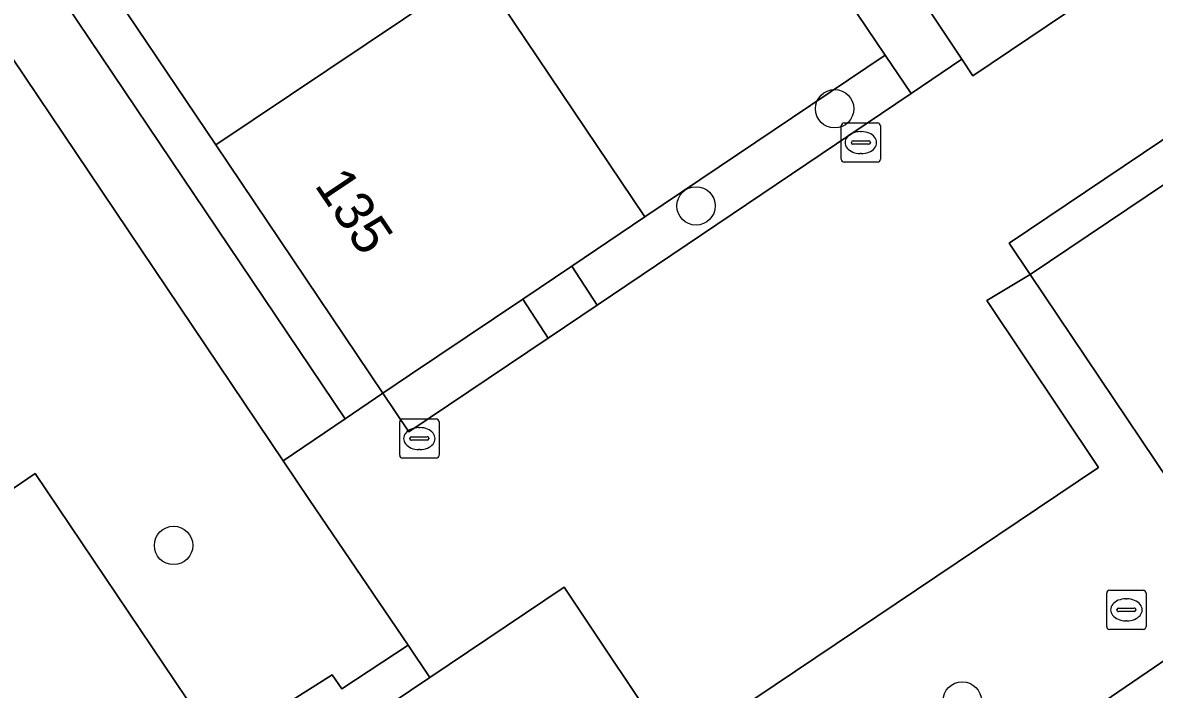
# Model space of a CAD drawing. Extents: x 158793 to 159888, y 384317 to 385256.
# Drawn here: x 159193.03 to 159221.85, y 384582.61 to 384599.59 of the extents above; entities that cross this region are included whole.
import ezdxf

# ---------------------------------------------------------------- set-up
doc = ezdxf.new("R2010")
doc.units = 0
for name, color, linetype in [('IMGEO_Boom', 7, 'Continuous'), ('IMGEO_Erf', 7, 'Continuous'), ('IMGEO_Groenvoorziening', 7, 'Continuous'), ('IMGEO_Kolk', 7, 'Continuous'), ('IMGEO_Pand', 7, 'Continuous'), ('IMGEO_Pand_nummerreeks', 7, 'Continuous'), ('IMGEO_Rijbaan_lokaal_open', 7, 'Continuous'), ('IMGEO_Rioolput', 7, 'Continuous'), ('IMGEO_Voetpad_gesloten', 7, 'Continuous'), ('IMGEO_Voetpad_open', 7, 'Continuous')]:
    doc.layers.add(name, color=color, linetype=linetype)

msp = doc.modelspace()

# ---------------------------------------------------------------- linework, layer by layer
at = {"layer": 'IMGEO_Boom'}
for centre in [(159213.705, 384597.396), (159210.177, 384594.923), (159196.875, 384586.273), (159216.954, 384582.311)]:
    msp.add_circle(centre, 0.489, dxfattribs=at)
at = {"layer": 'IMGEO_Erf'}
msp.add_lwpolyline([(159189.5, 384636.563), (159183.38, 384632.567), (159187.63, 384626.246), (159191.879, 384619.926), (159196.129, 384613.605), (159200.378, 384607.285), (159204.628, 384600.965), (159208.877, 384594.644), (159214.996, 384598.764)], close=True, dxfattribs=at)
at = {"layer": 'IMGEO_Groenvoorziening'}
for points in [[(159245.073, 384674.375), (159284.084, 384616.156), (159275.927, 384610.681), (159273.311, 384614.477), (159265.419, 384609.219), (159264.866, 384609.954), (159259.381, 384606.275), (159260.51, 384604.607), (159254.969, 384600.946), (159255.845, 384599.623), (159254.824, 384599.006), (159227.4, 384580.648), (159223.505, 384586.498), (159223.273, 384586.343), (159218.681, 384593.177), (159217.583, 384592.512), (159220.423, 384588.255), (159209.629, 384581), (159206.819, 384585.213), (159203.401, 384582.912), (159198.891, 384579.876)], [(159218.552, 384602.596), (159215.624, 384600.655), (159216.947, 384598.656), (159217.228, 384598.232), (159220.077, 384600.155)], [(159208.686, 384574.19), (159223.666, 384584.415), (159228.726, 384576.872), (159242.691, 384586.237)]]:
    msp.add_lwpolyline(points, dxfattribs=at)
for points in [[(159184.844, 384610.474), (159149.937, 384586.778), (159139.375, 384579.667), (159141.123, 384576.932), (159150.625, 384583.433), (159151.747, 384581.759), (159165.041, 384590.724), (159170.605, 384582.437), (159174.689, 384585.159), (159179.297, 384578.512), (159193.347, 384588.107), (159197.808, 384581.483), (159198.988, 384582.307), (159199.249, 384581.925), (159200.917, 384582.98), (159201.158, 384582.618), (159202.847, 384583.73), (159200.329, 384587.446), (159199.667, 384588.43)], [(159215.656, 384597.786), (159214.996, 384598.764), (159208.877, 384594.644), (159207.011, 384593.387), (159207.663, 384592.398)], [(159206.415, 384591.557), (159205.763, 384592.546), (159202.885, 384590.608), (159202.203, 384590.149), (159202.865, 384589.164)]]:
    msp.add_lwpolyline(points, close=True, dxfattribs=at)
at = {"layer": 'IMGEO_Kolk'}
for p, q in [((159213.873, 384596.109), (159213.873, 384596.961)), ((159213.948, 384597.035), (159214.8, 384597.035)), ((159214.874, 384596.961), (159214.874, 384596.109)), ((159214.361, 384596.815), (159214.386, 384596.815)), ((159214.132, 384596.529), (159214.132, 384596.541)), ((159214.57, 384596.492), (159214.172, 384596.492)), ((159214.175, 384596.578), (159214.573, 384596.578)), ((159214.616, 384596.541), (159214.616, 384596.529)), ((159214.384, 384596.255), (159214.359, 384596.255)), ((159214.8, 384596.035), (159213.948, 384596.035)), ((159202.707, 384589.496), (159203.559, 384589.496)), ((159202.632, 384588.57), (159202.632, 384589.422)), ((159203.12, 384589.276), (159203.145, 384589.276)), ((159203.633, 384589.422), (159203.633, 384588.57)), ((159202.891, 384588.99), (159202.891, 384589.002)), ((159203.329, 384588.953), (159202.931, 384588.953)), ((159202.934, 384589.039), (159203.332, 384589.039)), ((159203.375, 384589.002), (159203.375, 384588.99)), ((159203.143, 384588.716), (159203.118, 384588.716)), ((159203.559, 384588.496), (159202.707, 384588.496))]:
    msp.add_line(p, q, dxfattribs=at)
for points in [[(159213.873, 384596.109), (159213.873, 384596.961)], [(159213.948, 384597.035), (159214.8, 384597.035)], [(159214.874, 384596.961), (159214.874, 384596.109)], [(159214.8, 384596.035), (159213.948, 384596.035)], [(159202.707, 384589.496), (159203.559, 384589.496)], [(159202.632, 384588.57), (159202.632, 384589.422)], [(159203.633, 384589.422), (159203.633, 384588.57)], [(159203.559, 384588.496), (159202.707, 384588.496)]]:
    msp.add_lwpolyline(points, dxfattribs=at)
for centre, radius, start, end in [((159213.95, 384596.959), 0.0765, 91.552, 178.448), ((159213.95, 384596.959), 0.0765, 91.552, 178.448), ((159214.798, 384596.959), 0.0765, 1.552, 88.448), ((159214.798, 384596.959), 0.0765, 1.552, 88.448), ((159214.172, 384596.538), 0.0403, 85.8775, 175.7526), ((159214.169, 384596.528), 0.0366, 178.938, 274.7102), ((159214.573, 384596.535), 0.043, 264.8664, 352.4533), ((159214.577, 384596.54), 0.0386, 1.7309, 96.639), ((159213.95, 384596.111), 0.0765, 181.552, 268.448), ((159213.95, 384596.111), 0.0765, 181.552, 268.448), ((159214.798, 384596.111), 0.0765, 271.552, 358.448), ((159214.798, 384596.111), 0.0765, 271.552, 358.448), ((159202.709, 384589.42), 0.0765, 91.552, 178.448), ((159202.709, 384589.42), 0.0765, 91.552, 178.448), ((159203.557, 384589.42), 0.0765, 1.552, 88.448), ((159203.557, 384589.42), 0.0765, 1.552, 88.448), ((159202.931, 384588.999), 0.0403, 85.8775, 175.7526), ((159202.928, 384588.989), 0.0366, 178.938, 274.7102), ((159203.332, 384588.996), 0.043, 264.8664, 352.4533), ((159203.336, 384589.001), 0.0386, 1.7309, 96.639), ((159202.709, 384588.572), 0.0765, 181.552, 268.448), ((159202.709, 384588.572), 0.0765, 181.552, 268.448), ((159203.557, 384588.572), 0.0765, 271.552, 358.448), ((159203.557, 384588.572), 0.0765, 271.552, 358.448)]:
    msp.add_arc(centre, radius, start, end, dxfattribs=at)
for centre, major_axis, ratio, start_param, end_param in [((159214.36, 384596.535), (-0.387, 0.002), 0.722429, 4.712389, 7.853982), ((159214.385, 384596.535), (-0.39, 0.002), 0.717154, 1.570796, 4.712389), ((159203.119, 384588.996), (-0.387, 0.002), 0.722429, 4.712389, 7.853982), ((159203.144, 384588.996), (-0.39, 0.002), 0.717154, 1.570796, 4.712389)]:
    msp.add_ellipse(centre, major_axis=major_axis, ratio=ratio, start_param=start_param, end_param=end_param, dxfattribs=at)
at = {"layer": 'IMGEO_Pand'}
for points in [[(159200.378, 384607.285), (159193.701, 384602.796), (159197.95, 384596.475), (159204.628, 384600.965)], [(159204.628, 384600.965), (159197.95, 384596.475), (159202.203, 384590.149), (159202.885, 384590.608), (159205.763, 384592.546), (159207.011, 384593.387), (159208.877, 384594.644)], [(159225.624, 384597.848), (159218.681, 384593.177), (159223.273, 384586.343), (159223.505, 384586.498), (159230.234, 384590.995)]]:
    msp.add_lwpolyline(points, close=True, dxfattribs=at)
at = {"layer": 'IMGEO_Rijbaan_lokaal_open'}
msp.add_lwpolyline([(159220.077, 384600.155), (159217.228, 384598.232), (159216.947, 384598.656), (159215.656, 384597.786), (159207.663, 384592.398), (159206.415, 384591.557), (159202.865, 384589.164), (159202.203, 384590.149), (159201.24, 384589.496), (159199.667, 384588.43), (159200.329, 384587.446), (159202.847, 384583.73), (159203.401, 384582.912), (159206.819, 384585.213), (159209.629, 384581), (159220.423, 384588.255), (159217.583, 384592.512), (159218.681, 384593.177), (159218.146, 384593.974), (159245.904, 384612.649)], dxfattribs=at)
at = {"layer": 'IMGEO_Rioolput'}
for p, q in [((159220.708, 384585.133), (159221.56, 384585.133)), ((159220.633, 384584.207), (159220.633, 384585.059)), ((159221.121, 384584.913), (159221.146, 384584.913)), ((159221.634, 384585.059), (159221.634, 384584.207)), ((159220.892, 384584.627), (159220.892, 384584.639)), ((159221.33, 384584.59), (159220.932, 384584.59)), ((159220.935, 384584.676), (159221.333, 384584.676)), ((159221.376, 384584.639), (159221.376, 384584.627)), ((159221.144, 384584.353), (159221.119, 384584.353)), ((159221.56, 384584.133), (159220.708, 384584.133))]:
    msp.add_line(p, q, dxfattribs=at)
for points in [[(159220.708, 384585.133), (159221.56, 384585.133)], [(159220.633, 384584.207), (159220.633, 384585.059)], [(159221.634, 384585.059), (159221.634, 384584.207)], [(159221.56, 384584.133), (159220.708, 384584.133)]]:
    msp.add_lwpolyline(points, dxfattribs=at)
for centre, radius, start, end in [((159220.71, 384585.057), 0.0765, 91.552, 178.448), ((159220.71, 384585.057), 0.0765, 91.552, 178.448), ((159221.558, 384585.057), 0.0765, 1.552, 88.448), ((159221.558, 384585.057), 0.0765, 1.552, 88.448), ((159220.932, 384584.636), 0.0403, 85.8775, 175.7526), ((159220.929, 384584.626), 0.0366, 178.938, 274.7102), ((159221.333, 384584.633), 0.043, 264.8664, 352.4533), ((159221.337, 384584.638), 0.0386, 1.7309, 96.639), ((159220.71, 384584.209), 0.0765, 181.552, 268.448), ((159220.71, 384584.209), 0.0765, 181.552, 268.448), ((159221.558, 384584.209), 0.0765, 271.552, 358.448), ((159221.558, 384584.209), 0.0765, 271.552, 358.448)]:
    msp.add_arc(centre, radius, start, end, dxfattribs=at)
for centre, major_axis, ratio, start_param, end_param in [((159221.12, 384584.633), (-0.387, 0.002), 0.722429, 4.712389, 7.853982), ((159221.145, 384584.633), (-0.39, 0.002), 0.717154, 1.570796, 4.712389)]:
    msp.add_ellipse(centre, major_axis=major_axis, ratio=ratio, start_param=start_param, end_param=end_param, dxfattribs=at)
at = {"layer": 'IMGEO_Voetpad_gesloten'}
for points in [[(159259, 384579.781), (159264.913, 384583.752), (159257.026, 384595.85), (159248.575, 384590.183), (159247.59, 384591.694), (159241.692, 384587.769), (159242.691, 384586.237), (159228.726, 384576.872), (159223.666, 384584.415), (159208.686, 384574.19)], [(159197.808, 384581.483), (159193.347, 384588.107), (159179.297, 384578.512), (159174.689, 384585.159), (159170.605, 384582.437), (159165.041, 384590.724), (159151.747, 384581.759), (159150.625, 384583.433), (159141.123, 384576.932)], [(159198.891, 384579.876), (159203.401, 384582.912), (159202.847, 384583.73), (159201.158, 384582.618), (159200.917, 384582.98), (159199.249, 384581.925)]]:
    msp.add_lwpolyline(points, dxfattribs=at)
at = {"layer": 'IMGEO_Voetpad_open'}
for points in [[(159189.5, 384636.563), (159214.996, 384598.764), (159215.656, 384597.786), (159216.947, 384598.656), (159215.624, 384600.655), (159209.726, 384609.51), (159208.644, 384611.068), (159201.442, 384621.858), (159200.364, 384623.414), (159203.215, 384625.336), (159209.792, 384629.775)], [(159184.844, 384610.474), (159199.667, 384588.43), (159201.24, 384589.496), (159185.263, 384613.249), (159175.767, 384627.444), (159176.706, 384628.077), (159176.084, 384629.066)]]:
    msp.add_lwpolyline(points, dxfattribs=at)
for points in [[(159189.452, 384609.117), (159185.203, 384615.437), (159180.954, 384621.758), (159176.706, 384628.077), (159175.767, 384627.444), (159185.263, 384613.249), (159201.24, 384589.496), (159202.203, 384590.149), (159197.95, 384596.475), (159193.701, 384602.796)], [(159239.509, 384607.189), (159246.451, 384611.86), (159245.904, 384612.649), (159218.146, 384593.974), (159218.681, 384593.177), (159225.624, 384597.848), (159232.566, 384602.519)], [(159207.011, 384593.387), (159205.763, 384592.546), (159206.415, 384591.557), (159207.663, 384592.398)]]:
    msp.add_lwpolyline(points, close=True, dxfattribs=at)

# ---------------------------------------------------------------- texts
at = {"layer": 'IMGEO_Pand_nummerreeks'}
msp.add_text('135', height=1, rotation=303.9132, dxfattribs=at).set_placement((159200.447, 384595.45))

doc.saveas('drawing.dxf')
